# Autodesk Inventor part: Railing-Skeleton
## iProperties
Created: 2006-02
Part Number: Railing-Skeleton
Document SubType Name: Modeling
Designer: 40664
Mass: 827758 g
Surface Area: 350137 cm^2
Volume: 827758 cm^3
Density: 1 g/cm^3
CSToolsMass: 828.0
CSToolsVolume: 827757655.0
CSToolsArea: 350137.0
Author: 40664
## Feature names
1. Extrusion2
2. Fillet1
3. Shell1
4. Extrusion3
5. Fillet2
6. Split1
7. Split2
8. Split3
9. Split4
10. Split5
